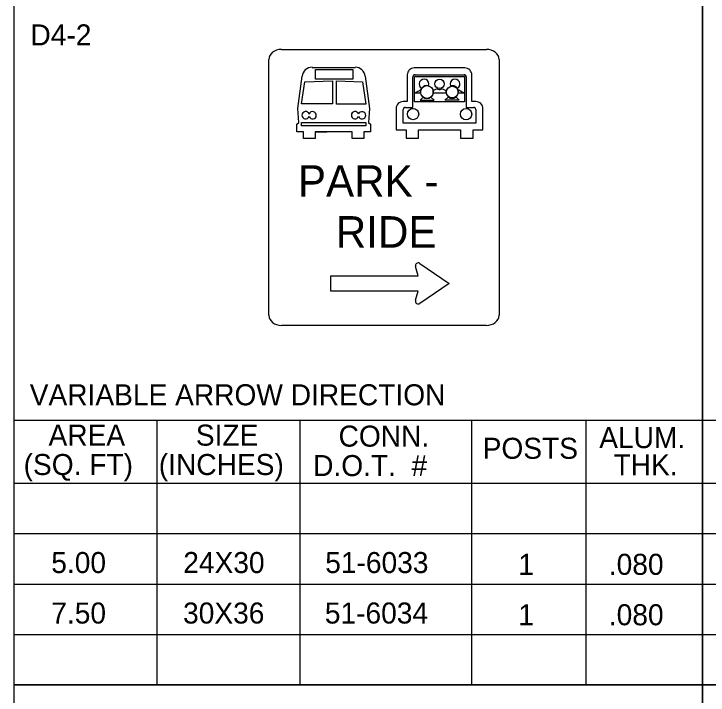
# Model space of a CAD drawing. Extents: x 0 to 2011, y -71 to 1183.
# Drawn here: x 214.5 to 320.2, y 598.9 to 702.5 of the extents above; entities that cross this region are included whole.
import ezdxf

# ---------------------------------------------------------------- set-up
doc = ezdxf.new("R2010")
doc.units = 0
for name, color, linetype in [('Level 1', 7, 'Continuous'), ('Level 2', 7, 'Continuous'), ('Level 5', 7, 'Continuous')]:
    doc.layers.add(name, color=color, linetype=linetype)

msp = doc.modelspace()

# ---------------------------------------------------------------- linework, layer by layer
at = {"layer": 'Level 1'}
for p, q in [((255.27, 697.11), (286.43, 697.11)), ((253.34, 656.66), (253.34, 695.57)), ((288.36, 695.57), (288.36, 656.66)), ((259.92, 694.37), (266.48, 694.37)), ((279.31, 694.29), (275.46, 694.29)), ((283.16, 694.29), (279.31, 694.29)), ((257.73, 688.1), (258.4, 693.02)), ((267.99, 693.01), (268.67, 688.1)), ((274.4, 693.23), (274.4, 689.17)), ((275.25, 688.29), (275.25, 692.93)), ((275.51, 689.11), (275.51, 692.93)), ((275.58, 693.26), (279.31, 693.26)), ((275.58, 692.99), (279.31, 692.99)), ((279.31, 693.26), (283.04, 693.26)), ((279.31, 692.99), (283.04, 692.99)), ((283.11, 692.93), (283.11, 689.11)), ((283.37, 692.93), (283.37, 688.29)), ((284.22, 689.17), (284.22, 693.23)), ((258.29, 688.81), (258.82, 692.18)), ((258.82, 692.18), (263.02, 692.31)), ((263.02, 692.31), (263.02, 688.81)), ((263.63, 688.8), (263.63, 692.31)), ((263.63, 692.31), (267.58, 692.19)), ((267.58, 692.19), (268.12, 688.77)), ((275.52, 690.45), (276.49, 690.99)), ((278.33, 690.87), (278.86, 691.13)), ((279.76, 691.13), (280.29, 690.87)), ((282.13, 690.99), (283.1, 690.45)), ((276.44, 690.45), (275.52, 690.45)), ((276.8, 689.85), (276.34, 689.37)), ((278.48, 689.37), (277.99, 689.86)), ((279.31, 690.45), (278.35, 690.45)), ((280.27, 690.45), (279.31, 690.45)), ((280.14, 689.37), (280.62, 689.86)), ((280.27, 690.45), (280.27, 690.45)), ((281.82, 689.85), (282.28, 689.37)), ((283.1, 690.45), (282.18, 690.45)), ((263.02, 688.81), (258.29, 688.81)), ((268.12, 688.77), (263.63, 688.8)), ((274.4, 689.17), (273.77, 689.17)), ((279.31, 689.11), (275.51, 689.11)), ((276.34, 689.37), (278.48, 689.37)), ((283.11, 689.11), (279.31, 689.11)), ((282.28, 689.37), (280.14, 689.37)), ((284.85, 689.17), (284.22, 689.17)), ((257.89, 685.97), (257.73, 688.1)), ((268.67, 688.1), (268.51, 685.97)), ((272.71, 688.11), (272.71, 684.87)), ((273.8, 685.89), (273.8, 687.96)), ((274.13, 688.29), (275.25, 688.29)), ((283.37, 688.29), (284.49, 688.29)), ((284.82, 687.96), (284.82, 685.89)), ((285.91, 684.87), (285.91, 688.11)), ((259.49, 687.31), (259.47, 687.27)), ((257.6, 685.71), (257.89, 685.97)), ((257.6, 684.56), (257.6, 685.71)), ((268.51, 685.97), (268.79, 685.71)), ((268.79, 685.71), (268.79, 684.56)), ((279.31, 685.89), (273.8, 685.89)), ((284.82, 685.89), (279.31, 685.89)), ((258.62, 684.56), (257.6, 684.56)), ((258.62, 683.55), (258.62, 684.56)), ((260.4, 684.56), (262.17, 684.56)), ((266, 684.56), (260.4, 684.56)), ((260.4, 684.56), (260.4, 683.55)), ((266, 683.55), (266, 684.56)), ((268.79, 684.56), (267.78, 684.56)), ((267.78, 684.56), (267.78, 683.55)), ((272.71, 684.87), (274.21, 684.87)), ((274.21, 684.87), (274.21, 683.61)), ((276.13, 683.61), (276.13, 684.87)), ((276.13, 684.87), (279.31, 684.87)), ((279.31, 684.87), (282.48, 684.87)), ((282.48, 684.87), (282.48, 683.61)), ((284.41, 683.61), (284.41, 684.87)), ((284.41, 684.87), (285.91, 684.87)), ((260.4, 683.55), (258.62, 683.55)), ((267.78, 683.55), (266, 683.55)), ((274.21, 683.61), (276.13, 683.61)), ((282.48, 683.61), (284.41, 683.61)), ((276.33, 664.56), (280.76, 661.51)), ((276.06, 662.68), (275.65, 664.06)), ((262.77, 660.34), (262.77, 662.68)), ((262.77, 662.68), (276.06, 662.68)), ((280.76, 661.51), (276.33, 658.47)), ((280.76, 661.51), (280.76, 661.51)), ((276.06, 660.34), (262.77, 660.34)), ((275.65, 658.96), (276.06, 660.34)), ((253.34, 656.66), (253.34, 656.66)), ((286.43, 655.11), (255.27, 655.11))]:
    msp.add_line(p, q, dxfattribs=at)
for points in [[(260.46, 694.07), (266.1, 694.07), (266.1, 692.57), (260.46, 692.57)], [(258.31, 685.97), (268.12, 685.97), (268.12, 685.49), (258.31, 685.49)]]:
    msp.add_lwpolyline(points, close=True, dxfattribs=at)
for centre, radius in [((279.31, 691.86), 0.724), ((277.39, 690.63), 0.971), ((281.24, 690.61), 0.89), ((275.28, 687.26), 0.855), ((283.34, 687.26), 0.861)]:
    msp.add_circle(centre, radius, dxfattribs=at)
for centre, radius, start, end in [((259.9, 692.87), 1.51, 89.5184, 174.4732), ((266.49, 692.87), 1.51, 5.5268, 90.4816), ((275.46, 693.23), 1.06, 89.9998, 180), ((283.16, 693.23), 1.06, 360, 90.0002), ((275.58, 692.93), 0.33, 90, 179.9999), ((275.58, 692.93), 0.066, 90, 179.9999), ((283.04, 692.93), 0.33, 0.0001, 90), ((283.04, 692.93), 0.066, 0.0001, 90), ((276.95, 691.84), 0.747, 338.1694, 241.5129), ((281.67, 691.84), 0.747, 298.4871, 201.8306), ((277.39, 690.63), 0.971, 157.7423, 190.3083), ((277.39, 690.63), 0.971, 74.7837, 144.8973), ((277.39, 690.63), 0.971, 349.691, 14.3149), ((279.31, 691.86), 0.851, 237.9547, 269.8201), ((279.31, 691.86), 0.851, 270.1799, 302.0453), ((281.23, 690.63), 0.971, 165.6851, 190.309), ((281.23, 690.63), 0.971, 35.1027, 105.2163), ((281.23, 690.63), 0.971, 349.6917, 22.2577), ((277.39, 690.63), 0.971, 232.6583, 308.4346), ((281.23, 690.63), 0.971, 231.5654, 307.3417), ((273.77, 688.11), 1.06, 89.9992, 180), ((284.85, 688.11), 1.06, 360, 90.0008), ((258.94, 687.09), 0.563, 18.4448, 339.8991), ((260, 687.08), 0.563, 199.0107, 155.9912), ((266.46, 687.09), 0.563, 19.0107, 339.8991), ((267.52, 687.08), 0.563, 199.0107, 159.8991), ((274.13, 687.96), 0.33, 89.9998, 180), ((284.49, 687.96), 0.33, 360, 90.0002), ((276.08, 664.19), 0.446, 55.5114, 196.6409), ((276.08, 658.83), 0.446, 163.3591, 304.4886)]:
    msp.add_arc(centre, radius, start, end, dxfattribs=at)
for centre, major_axis, start_param, end_param in [((255.27, 695.57), (-1.93, 0), 4.712389, 6.283185), ((286.43, 695.57), (1.93, 0), 0, 1.570796), ((255.27, 656.66), (-1.93, 0), 0, 1.570796), ((286.43, 656.66), (1.93, 0), 4.712389, 6.283185)]:
    msp.add_ellipse(centre, major_axis=major_axis, ratio=0.8, start_param=start_param, end_param=end_param, dxfattribs=at)
at = {"layer": 'Level 2'}
for p, q in [((276.95, 691.84), (276.95, 691.84)), ((279.31, 691.85), (279.31, 691.85)), ((279.31, 691.85), (279.31, 691.85)), ((281.67, 691.84), (281.67, 691.84)), ((277.39, 690.63), (277.39, 690.63)), ((281.23, 690.63), (281.23, 690.63)), ((214.55, 640.71), (319.3, 640.71)), ((236.3, 640.71), (236.3, 600.44)), ((258.05, 640.71), (258.05, 600.44)), ((284.15, 640.71), (284.15, 600.44)), ((301.55, 640.71), (301.55, 600.44)), ((319.3, 640.71), (424.05, 640.71)), ((214.55, 631.12), (319.3, 631.12)), ((319.3, 631.12), (424.05, 631.12)), ((214.55, 623.45), (319.3, 623.45)), ((319.3, 623.45), (424.05, 623.45)), ((214.55, 615.78), (319.3, 615.78)), ((319.3, 615.78), (424.05, 615.78)), ((214.55, 608.11), (319.3, 608.11)), ((319.3, 608.11), (424.05, 608.11))]:
    msp.add_line(p, q, dxfattribs=at)
for points in [[(319.3, 704.06), (214.55, 704.06), (214.55, 600.44), (319.3, 600.44)], [(424.05, 704.06), (319.3, 704.06), (319.3, 600.44), (424.05, 600.44)], [(319.3, 600.44), (214.55, 600.44), (214.55, 496.81), (319.3, 496.81)], [(424.05, 600.44), (319.3, 600.44), (319.3, 496.81), (424.05, 496.81)]]:
    msp.add_lwpolyline(points, close=True, dxfattribs=at)
at = {"layer": 'Level 5'}
msp.add_line((214.55, 830), (214.55, 496.81), dxfattribs=at)

# ---------------------------------------------------------------- texts
at = {"layer": 'Level 2'}
for s, height, p in [('D4-2', 3.2, (217.07, 697.71)), ('PARK -', 4.8, (257.76, 674.68)), ('RIDE', 4.8, (263.52, 666.94)), ('VARIABLE ARROW DIRECTION', 3.2, (216.96, 642.97)), ('SIZE', 3.2, (242.23, 636.83)), ('AREA', 3.2, (219.82, 636.83)), ('CONN.', 3.2, (263.95, 636.68)), ('ALUM.', 3.2, (303.61, 636.45)), ('POSTS', 3.2, (285.87, 634.83)), ('(SQ. FT)', 3.2, (216.03, 632.36)), ('(INCHES)', 3.2, (236.6, 632.36)), ('D.O.T.  #', 3.2, (260.08, 632.2)), ('THK.', 3.2, (305.79, 632.31))]:
    msp.add_text(s, height=height, dxfattribs=at).set_placement(p)
at = {"layer": 'Level 5'}
for s, p in [(' 5.00', (219.05, 617.45)), ('24X30', (240.32, 617.45)), ('51-6033', (261.92, 617.45)), ('1', (291.29, 617.18)), ('.080', (305.07, 617.18)), (' 7.50', (219.05, 609.77)), ('30X36', (240.29, 609.77)), ('51-6034', (261.86, 609.77)), ('1', (291.29, 609.51)), ('.080', (305.07, 609.51))]:
    msp.add_text(s, height=3.2, dxfattribs=at).set_placement(p)

doc.saveas('drawing.dxf')
